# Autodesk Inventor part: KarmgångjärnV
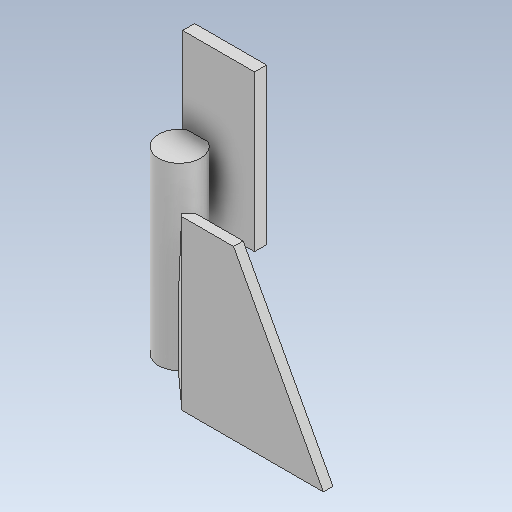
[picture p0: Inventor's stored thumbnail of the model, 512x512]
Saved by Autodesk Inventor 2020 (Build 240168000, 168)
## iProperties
Created: 2019-06
Part Number: KarmgångjärnV
Material: Generic
Document SubType Name: Modeling
Designer: cl
Density: 1 g/cm^3
Appearance: Default
Author: cl
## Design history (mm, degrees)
sketch "Sketch1"
  geometry: L1 (0, 8)-(115, 8); L2 (118.071, 0)-(0, 0); L3 (0, 0)-(0, 8); L4 (115, 8)-(142.016, 32.325); L5 (115, 8)-(126.561, 8); L6 (118.071, 0)-(147.369, 26.38); L7 (142.016, 32.325)-(147.369, 26.38); L8 (0, 0)-(250, 0); L9 (0, -8)-(115, -8); L10 (115, -8)-(142.016, -32.325); L11 (118.071, 0)-(147.369, -26.38); L12 (142.016, -32.325)-(147.369, -26.38); L13 (0, 0)-(0, -8); C1 r 17.5 at (160, 40); C2 r 17.5 at (160, -40); 3 further points
  constraints: 26 end point, 5 symmetric about line, 3 coincident, 2 centre point, 2 horizontal, 2 parallel, 1 perpendicular, 1 point on line, 1 vertical, 1 other
  dimensions: "d0" = 35 diameter of C1; "d1" = 40 vertical distance of point (0, 0) C1.centre; "d2" = 160 horizontal distance of point (0, 0) C1.centre; "d3" = 42 deg angle of L5 L4; "d4" = 8 distance between parallel lines of L4 L6; "d5" = 8 distance between parallel lines of L1 L2; "d6" = 115 horizontal distance of point (0, 0) L1.end; "d7" = 1 distance edge to line of C1 L7; "d8" = 90 deg angle of L4 L7; "d9" = 27.76238 distance from line of L5.end L7; "d10" = 250 distance of L2.end L8.end
extrude "Extrusion1" new body sketch "Sketch1" distance "d11" = 140; taper "d12" = 0 deg
thicken "Thicken1" dims "d13" = 10, "d14" = 10
chamfer "Chamfer1" distance "d15" = 75; stored, may be unused: second distance "d16" = 140, angle "d17" = 45 deg
sketch "Sketch2"
  geometry: L1 (-36.354, 0)-(-36.354, 140) reference; L2 (-36.354, 140)-(0, 56); L3 (0, 0)-(0, 140) reference; L4 (-36.354, 0)-(0, 0) reference; L5 (0, 140)-(-39.425, 140) reference; L6 (-36.354, 140)-(0, 140); L7 (0, 140)-(0, 56); L8 (1, 0)-(1, 150) reference; 1 further point
  constraints: 6 end point, 1 horizontal, 1 parallel, 1 point on line
  dimensions: "d18" = 56 distance from line of L4 L2.end
extrude "Extrusion2" cut sketch "Sketch2" extent not by distance; stored distance "d19" = 0; taper "d20" = 0 deg
workplane "Work Plane1"
sketch "Sketch4"
  geometry: L1 (112.5, 220)-(172.5, 220); L2 (172.5, 220)-(172.5, 90); L3 (172.5, 90)-(112.5, 90); L4 (112.5, 90)-(112.5, 220); L5 (177.5, 150)-(142.5, 150) reference; 1 further point
  constraints: 8 end point, 2 parallel, 1 horizontal, 1 perpendicular
  dimensions: "d27" = 60 distance of L2.end L3.end; "d28" = 130 distance of L1.end L2.end; "d30" = 70 distance between parallel lines of L1 L5; "d33" = 5 distance from line of L5.start L2
extrude "Extrusion3" join sketch "Sketch4" distance "d31" = 10; taper "d32" = 0 deg
body "Solid1"
other parameters: "d26" = 57
